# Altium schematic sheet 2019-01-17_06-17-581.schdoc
size 405 x 220 mm; SheetNumber: 1; SheetTotal: 1
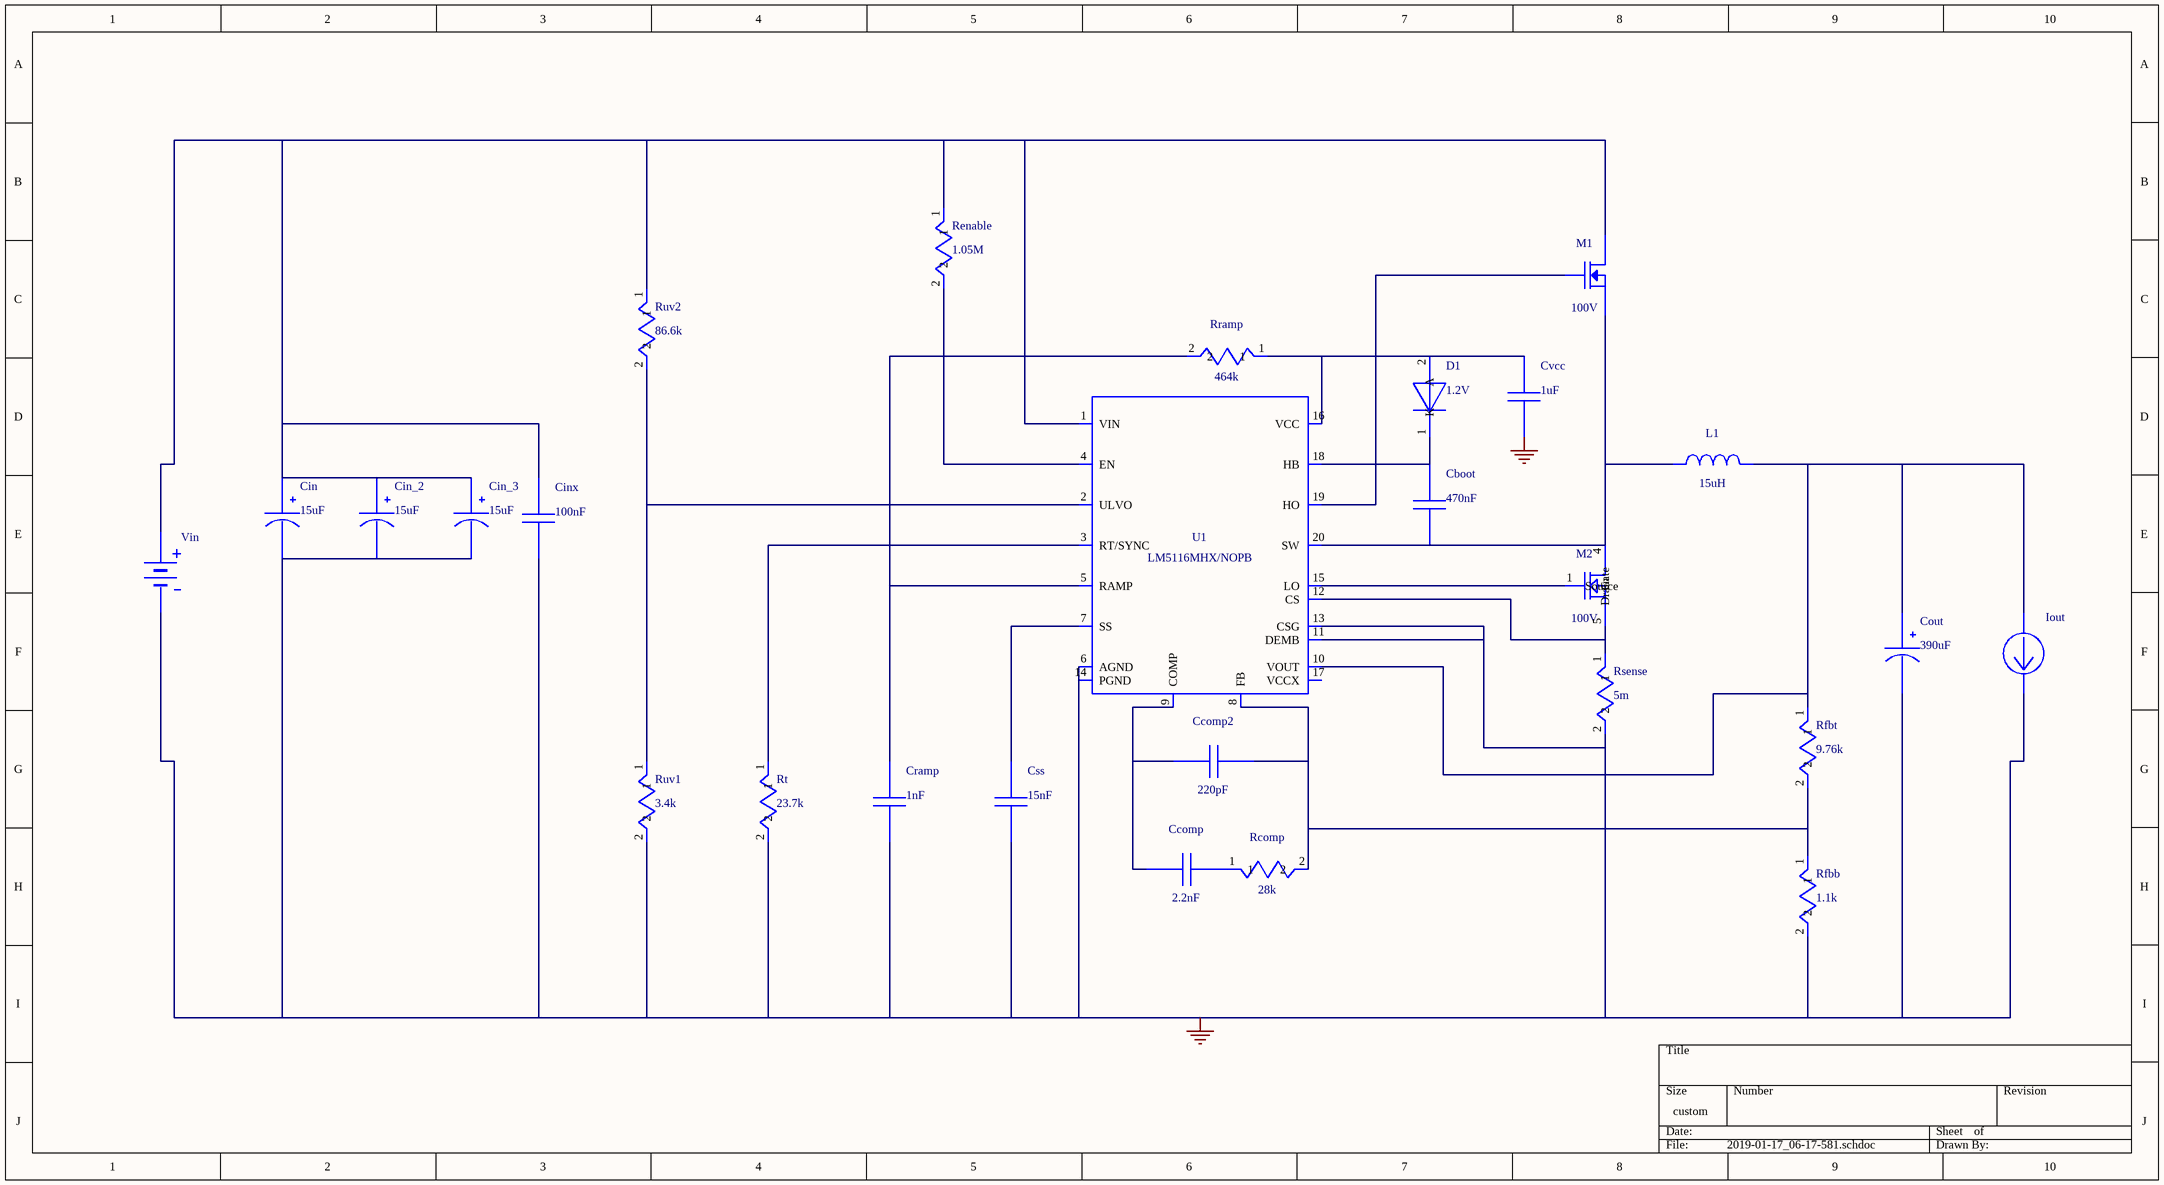
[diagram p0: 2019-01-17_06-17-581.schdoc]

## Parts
Cboot  value 470nF  (hidden comment: ECPU1C474MA5)
Ccomp  value 2.2nF  (hidden comment: C2012C0G1H222K060AA)
Ccomp2  value 220pF  (hidden comment: CL05C221JA5NNNC)
Cin  value 15uF  (hidden comment: 100SXV15M)
Cin_2  value 15uF  (hidden comment: 100SXV15M)
Cin_3  value 15uF  (hidden comment: 100SXV15M)
Cinx  value 100nF  (hidden comment: HMK212B7104KG-T)
Cout  value 390uF  (hidden comment: 20SVPF390M)
Cramp  value 1nF  (hidden comment: GRM2165C1H102JA01J)
Css  value 15nF  (hidden comment: C2012C0G1H153J085AA)
Cvcc  value 1uF  (hidden comment: TMK212BJ105KG-T)
D1  value 1.2V  (hidden comment: UFS180JE3/TR13)
Iout  WB_CURRENT_LOAD  (value not drawn)
L1  value 15uH  (hidden comment: SER2918H-153KL)
M1  value 100V  (hidden comment: CSD19534Q5A)
M2  value 100V  (hidden comment: FDWS86068-F085)
Rcomp  value 28k  (hidden comment: CRCW040228K0FKED)
Renable  value 1.05M  (hidden comment: CRCW04021M05FKED)
Rfbb  value 1.1k  (hidden comment: ERJ-6ENF1101V)
Rfbt  value 9.76k  (hidden comment: CRCW04029K76FKED)
Rramp  value 464k  (hidden comment: CRCW0402464KFKED)
Rsense  value 5m  (hidden comment: PRL1632-R005-F-T1)
Rt  value 23.7k  (hidden comment: ERJ-2RKF2372X)
Ruv1  value 3.4k  (hidden comment: CRCW04023K40FKED)
Ruv2  value 86.6k  (hidden comment: AC0402FR-0786K6L)
U1  LM5116MHX/NOPB
Vin  WB_BATTERY  (value not drawn)

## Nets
0: Cin.2(-) Cin_2.2(-) Cin_3.2(-) Cinx.2 Cout.2(-) Cramp.2 Css.2 Cvcc.2 Iout.2(-) Rfbb.2 Rsense.2 Rt.2 Ruv1.2 U1.6(AGND) U1.11(DEMB) U1.13(CSG) U1.14(PGND) U1.21(EP) Vin.2(-)
NetCboot_1: Cboot.1 D1.1(K) U1.18(HB)
NetCboot_2: Cboot.2 L1.1 M1.1(Source) M1.2(Source) M1.3(Source) M2.4(Gate) U1.20(SW)
NetCcomp2_2: Ccomp2.2 Rcomp.2 Rfbb.1 Rfbt.2 U1.8(FB)
NetCcomp_1: Ccomp.1 Ccomp2.1 U1.9(COMP)
NetCcomp_2: Ccomp.2 Rcomp.1
NetCin_1: Cin.1(+) Cin_2.1(+) Cin_3.1(+) Cinx.1 M1.5(Drain) M1.6(Drain) M1.7(Drain) M1.8(Drain) M1.9(Drain) Renable.1 Ruv2.1 U1.1(VIN) Vin.1(+)
NetCout_1: Cout.1(+) Iout.1(+) L1.2 Rfbt.1 U1.10(VOUT)
NetCramp_1: Cramp.1 Rramp.2 U1.5(RAMP)
NetCss_1: Css.1 U1.7(SS)
NetCvcc_1: Cvcc.1 D1.2(A) Rramp.1 U1.16(VCC)
NetM1_4: M1.4(Gate) U1.19(HO)
NetM2_1: M2.1(Source) M2.2(Source) M2.3(Source) U1.15(LO)
NetM2_5: M2.5(Drain) M2.6(Drain) M2.7(Drain) M2.8(Drain) Rsense.1 U1.12(CS)
NetRenable_2: Renable.2 U1.4(EN)
NetRt_1: Rt.1 U1.3(RT/SYNC)
NetRuv1_1: Ruv1.1 Ruv2.2 U1.2(ULVO)

Not connected (* = marked no-connect by the designer): U1 17(VCCX)

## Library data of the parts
Cboot = ECPU1C474MA5: Manufacturer Name: Panasonic
Ccomp = C2012C0G1H222K060AA: C2012C0G1H222K06; Manufacturer Name: TDK
Ccomp2 = CL05C221JA5NNNC: Manufacturer Name: Samsung Electro-Mechanics
Cin Cin_2 Cin_3 = 100SXV15M: Manufacturer Name: Panasonic
Cinx = HMK212B7104KG-T: Manufacturer Name: Taiyo Yuden
Cout = 20SVPF390M: Manufacturer Name: Panasonic
Cramp = GRM2165C1H102JA01J: GRM2165C1H102JA0; Manufacturer Name: MuRata
Css = C2012C0G1H153J085AA: C2012C0G1H153J08; Manufacturer Name: TDK
Cvcc = TMK212BJ105KG-T: Manufacturer Name: Taiyo Yuden
D1 = UFS180JE3/TR13: Manufacturer Name: Microsemi
L1 = SER2918H-153KL: Manufacturer Name: Coilcraft
M1 = CSD19534Q5A: Manufacturer Name: Texas Instruments
M2 = FDWS86068-F085: Manufacturer Name: ON Semiconductor
Rcomp = CRCW040228K0FKED: Manufacturer Name: Vishay-Dale
Renable = CRCW04021M05FKED: Manufacturer Name: Vishay-Dale
Rfbb = ERJ-6ENF1101V: Manufacturer Name: Panasonic
Rfbt = CRCW04029K76FKED: Manufacturer Name: Vishay-Dale
Rramp = CRCW0402464KFKED: Manufacturer Name: Vishay-Dale
Rsense = PRL1632-R005-F-T1: PRL1632-R005-F-T; Manufacturer Name: Susumu Co Ltd
Rt = ERJ-2RKF2372X: Manufacturer Name: Panasonic
Ruv1 = CRCW04023K40FKED: Manufacturer Name: Vishay-Dale
Ruv2 = AC0402FR-0786K6L: Manufacturer Name: Yageo
U1 = LM5116MHX/NOPB: Manufacturer Name: Texas Instruments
